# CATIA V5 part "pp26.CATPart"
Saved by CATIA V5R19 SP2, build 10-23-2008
Part number: pp26
Publications: "Line.2", "Point.2", "Plane.1", "Line.3"
Bounding box of the stored display mesh (mm): x -20 to 0, y -100 to 100, z -50 to 50
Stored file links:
  C:\Users\Welcome\Documents\thinkm2\pp26.CATPart
  C:\Users\Welcome\Documents\thinkm2\Brasmeca.CATProduct
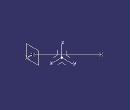
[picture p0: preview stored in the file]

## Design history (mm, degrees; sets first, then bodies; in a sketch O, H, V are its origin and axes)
AxisSystem1: origin (0, 0, 0), X (1, 0, 0), Y (0, 1, 0), Z (0, 0, 1)
Set1
  Point1: linked copy from another document
  Point2: linked copy from another document
Body1 (main body)
  Line1: type PtDir, RefPoint Point1, Direction edge [XY plane of AxisSystem1 | ZX plane of AxisSystem1], Start 0, End -20
  Point3: type OnCurve, Support Line1, Length 5
  Plane1: type Normal, Curve Line1, RefPoint Point3
  Line2: type PtPt, FirstPoint Point3, SecondPoint Point2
